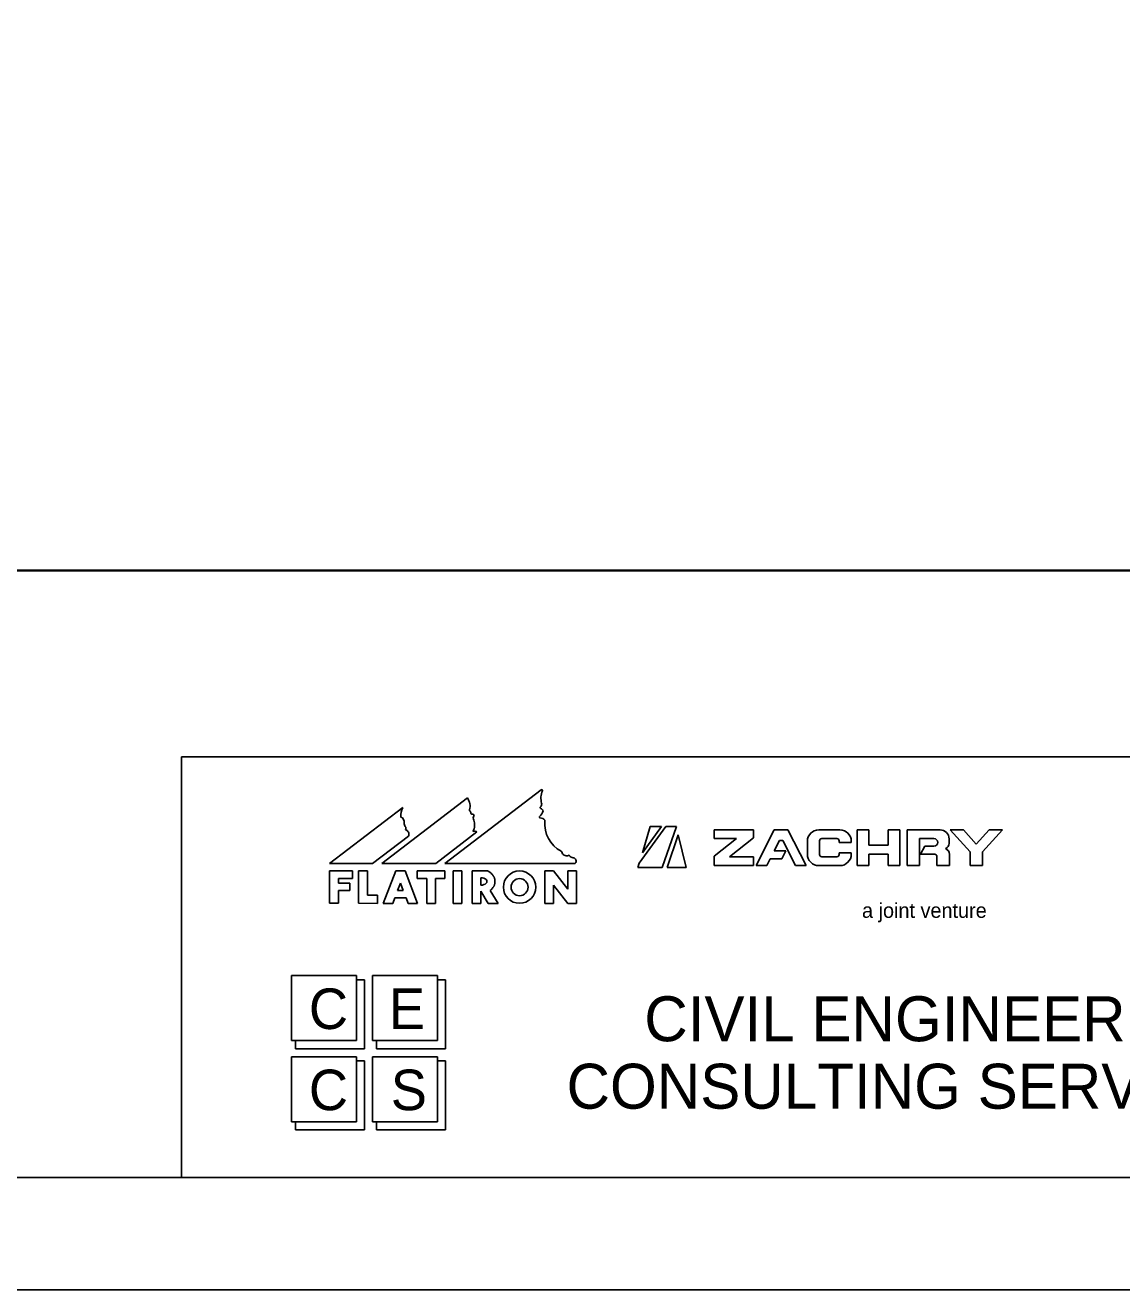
# Model space of a CAD drawing. Extents: x -2251 to 10196, y -13470 to 1199.
# Drawn here: x 1279.1 to 1522.8, y -2925.6 to -2644.4 of the extents above; entities that cross this region are included whole.
import ezdxf

# ---------------------------------------------------------------- set-up
doc = ezdxf.new("R2010")
doc.units = 0
for name, color, linetype in [('Level 3', 7, 'Continuous'), ('RD_SHT_Bndy', 7, 'Continuous'), ('RD_SHT_Iplotshp', 7, 'Continuous'), ('RD_SHT_Logo', 7, 'Continuous'), ('RD_SHT_Misc1', 7, 'Continuous'), ('RD_SHT_Snap', 7, 'Continuous'), ('RD_SHT_TX', 7, 'Continuous'), ('RD_TX_RoadID', 7, 'Continuous')]:
    doc.layers.add(name, color=color, linetype=linetype)

msp = doc.modelspace()

# ---------------------------------------------------------------- linework, layer by layer
at = {"layer": 'Level 3'}
msp.add_line((1465.07, -2863.99), (1465.07, -2863.99), dxfattribs=at)
msp.add_line((1465.07, -2863.99), (1465.07, -2863.99), dxfattribs=at)
msp.add_line((1465.07, -2863.99), (1465.07, -2863.99), dxfattribs=at)
msp.add_line((1465.07, -2863.99), (1465.07, -2863.99), dxfattribs=at)
at = {"layer": 'RD_SHT_Bndy'}
for p, q in [((103.1, -2900.65), (1778.1, -2900.65)), ((1791.65, -2925.65), (31.65, -2925.65))]:
    msp.add_line(p, q, dxfattribs=at)
msp.add_lwpolyline([(153.4, -1901.26), (1731.08, -1901.26), (1731.08, -2765.57), (153.4, -2765.57)], close=True, dxfattribs=at)
at = {"layer": 'RD_SHT_Iplotshp'}
msp.add_lwpolyline([(-3.35, -1825.65), (1796.65, -1825.65), (1796.65, -2925.65), (-3.35, -2925.65)], close=True, dxfattribs=at)
at = {"layer": 'RD_SHT_Logo'}
for p, q in [((1372.32, -2830.86), (1393.74, -2814.44)), ((1377.35, -2816.27), (1358.31, -2830.86)), ((1346.7, -2830.86), (1362.98, -2818.38)), ((1415.56, -2830.77), (1421.47, -2822.59)), ((1420.48, -2822.59), (1416.24, -2828.47)), ((1416.24, -2828.47), (1417.96, -2822.59)), ((1417.96, -2822.59), (1420.48, -2822.59)), ((1423.82, -2822.59), (1420.68, -2831.76)), ((1421.47, -2822.59), (1423.82, -2822.59)), ((1440.93, -2823.35), (1432.22, -2823.35)), ((1432.22, -2823.35), (1432.22, -2825.3)), ((1440.93, -2825.16), (1440.93, -2823.35)), ((1445.58, -2823.35), (1441.53, -2831.3)), ((1448.58, -2823.35), (1445.58, -2823.35)), ((1452.63, -2831.3), (1448.58, -2823.35)), ((1455.44, -2823.35), (1460.18, -2823.35)), ((1466.62, -2823.35), (1464.02, -2823.35)), ((1464.02, -2823.35), (1464.02, -2831.3)), ((1466.62, -2826.8), (1466.62, -2823.35)), ((1470.9, -2823.35), (1470.9, -2826.8)), ((1473.51, -2823.35), (1470.9, -2823.35)), ((1473.5, -2831.3), (1473.51, -2823.35)), ((1482.43, -2823.35), (1475.13, -2823.35)), ((1475.13, -2823.35), (1475.13, -2831.3)), ((1484.68, -2823.35), (1487.64, -2823.35)), ((1489.08, -2828.24), (1484.68, -2823.35)), ((1487.64, -2823.35), (1490.48, -2826.51)), ((1490.48, -2826.51), (1493.32, -2823.35)), ((1496.28, -2823.35), (1491.88, -2828.24)), ((1493.32, -2823.35), (1496.28, -2823.35)), ((1364.27, -2824.74), (1356.29, -2830.86)), ((1370.3, -2830.86), (1379.48, -2823.82)), ((1424.24, -2824.44), (1421.74, -2831.76)), ((1425.99, -2831.76), (1424.24, -2824.44)), ((1437.2, -2825.3), (1432.22, -2829.24)), ((1432.22, -2825.3), (1437.2, -2825.3)), ((1435.63, -2829.35), (1440.93, -2825.16)), ((1445.57, -2827.99), (1446.71, -2825.75)), ((1446.71, -2825.75), (1447.44, -2825.75)), ((1447.44, -2825.75), (1450.27, -2831.3)), ((1452.94, -2828.8), (1452.94, -2825.85)), ((1455.64, -2825.8), (1455.64, -2828.85)), ((1459.48, -2825.3), (1456.14, -2825.3)), ((1459.98, -2826.15), (1459.98, -2825.8)), ((1462.68, -2826.15), (1459.98, -2826.15)), ((1462.68, -2825.85), (1462.68, -2826.15)), ((1477.83, -2831.3), (1477.83, -2825.31)), ((1477.83, -2825.31), (1481.07, -2825.31)), ((1484.43, -2826.36), (1484.43, -2825.35)), ((1432.22, -2829.24), (1432.22, -2831.3)), ((1440.93, -2829.35), (1435.63, -2829.35)), ((1440.93, -2831.3), (1440.93, -2829.35)), ((1448.15, -2827.99), (1445.57, -2827.99)), ((1447.23, -2829.79), (1448.15, -2827.99)), ((1456.14, -2829.35), (1459.48, -2829.35)), ((1459.98, -2828.5), (1462.68, -2828.5)), ((1459.98, -2828.85), (1459.98, -2828.5)), ((1462.68, -2828.5), (1462.68, -2828.8)), ((1470.9, -2826.8), (1466.62, -2826.8)), ((1466.62, -2831.3), (1466.62, -2828.8)), ((1466.62, -2828.8), (1470.9, -2828.8)), ((1470.9, -2828.8), (1470.9, -2831.3)), ((1479.03, -2826.97), (1478.11, -2828.77)), ((1478.11, -2828.77), (1481.24, -2828.77)), ((1481.07, -2826.97), (1479.03, -2826.97)), ((1481.74, -2829.27), (1481.74, -2831.3)), ((1483.68, -2827.6), (1483.68, -2827.47)), ((1484.54, -2831.3), (1484.54, -2828.76)), ((1489.08, -2831.3), (1489.08, -2828.24)), ((1491.88, -2828.24), (1491.88, -2831.3)), ((1356.29, -2830.86), (1346.7, -2830.86)), ((1358.31, -2830.86), (1370.3, -2830.86)), ((1401.19, -2830.86), (1372.32, -2830.86)), ((1415.27, -2831.76), (1415.56, -2830.77)), ((1420.68, -2831.76), (1415.27, -2831.76)), ((1421.74, -2831.76), (1425.99, -2831.76)), ((1432.22, -2831.3), (1440.93, -2831.3)), ((1441.53, -2831.3), (1443.88, -2831.3)), ((1443.88, -2831.3), (1444.65, -2829.79)), ((1444.65, -2829.79), (1447.23, -2829.79)), ((1450.27, -2831.3), (1452.63, -2831.3)), ((1460.18, -2831.3), (1455.44, -2831.3)), ((1464.02, -2831.3), (1466.62, -2831.3)), ((1470.9, -2831.3), (1473.5, -2831.3)), ((1475.13, -2831.3), (1477.83, -2831.3)), ((1481.74, -2831.3), (1484.54, -2831.3)), ((1491.88, -2831.3), (1489.08, -2831.3)), ((1346.72, -2839.7), (1346.72, -2832.5)), ((1346.72, -2832.5), (1351.82, -2832.5)), ((1351.82, -2834.15), (1348.67, -2834.15)), ((1348.67, -2834.15), (1348.67, -2835.21)), ((1351.82, -2832.5), (1351.82, -2834.15)), ((1355.12, -2832.5), (1353.17, -2832.5)), ((1353.17, -2832.5), (1353.17, -2839.7)), ((1355.12, -2837.9), (1355.12, -2832.5)), ((1361.42, -2832.5), (1358.65, -2839.71)), ((1363.52, -2832.5), (1361.42, -2832.5)), ((1366.28, -2839.71), (1363.52, -2832.5)), ((1366.22, -2834.15), (1366.22, -2832.5)), ((1366.22, -2832.5), (1372.37, -2832.5)), ((1368.32, -2834.15), (1366.22, -2834.15)), ((1368.32, -2839.71), (1368.32, -2834.15)), ((1372.37, -2834.15), (1370.27, -2834.15)), ((1370.27, -2834.15), (1370.27, -2839.71)), ((1372.37, -2832.5), (1372.37, -2834.15)), ((1374.17, -2839.71), (1374.17, -2832.5)), ((1374.17, -2832.5), (1376.12, -2832.5)), ((1376.12, -2832.5), (1376.12, -2839.71)), ((1381.8, -2832.5), (1378.38, -2832.5)), ((1378.38, -2832.5), (1378.38, -2839.71)), ((1380.33, -2835.66), (1380.33, -2834.01)), ((1396.52, -2832.5), (1394.57, -2832.5)), ((1394.57, -2832.5), (1394.57, -2839.71)), ((1399.67, -2836.53), (1396.52, -2832.5)), ((1401.62, -2832.5), (1399.67, -2832.5)), ((1399.67, -2832.5), (1399.67, -2836.53)), ((1401.62, -2839.71), (1401.62, -2832.5)), ((1348.67, -2835.21), (1351.22, -2835.21)), ((1351.22, -2836.86), (1348.67, -2836.86)), ((1348.67, -2836.86), (1348.67, -2839.7)), ((1351.22, -2835.21), (1351.22, -2836.86)), ((1361.83, -2836.86), (1362.47, -2835.2)), ((1363.1, -2836.86), (1361.83, -2836.86)), ((1362.47, -2835.2), (1363.1, -2836.86)), ((1380.33, -2839.71), (1380.33, -2837.02)), ((1380.33, -2837.02), (1381.94, -2839.71)), ((1384.16, -2839.71), (1382.43, -2836.82)), ((1396.52, -2839.71), (1396.52, -2835.67)), ((1396.52, -2835.67), (1399.67, -2839.71)), ((1348.67, -2839.7), (1346.72, -2839.7)), ((1353.17, -2839.7), (1357.37, -2839.71)), ((1357.37, -2837.9), (1355.12, -2837.9)), ((1357.37, -2839.71), (1357.37, -2837.9)), ((1358.65, -2839.71), (1360.74, -2839.71)), ((1360.74, -2839.71), (1361.2, -2838.51)), ((1361.2, -2838.51), (1363.74, -2838.51)), ((1363.74, -2838.51), (1364.2, -2839.71)), ((1364.2, -2839.71), (1366.28, -2839.71)), ((1370.27, -2839.71), (1368.32, -2839.71)), ((1376.12, -2839.71), (1374.17, -2839.71)), ((1378.38, -2839.71), (1380.33, -2839.71)), ((1381.94, -2839.71), (1384.16, -2839.71)), ((1394.57, -2839.71), (1396.52, -2839.71)), ((1399.67, -2839.71), (1401.62, -2839.71)), ((1352.67, -2855.79), (1338.28, -2855.79)), ((1338.28, -2855.79), (1338.28, -2870.23)), ((1352.67, -2870.23), (1352.67, -2855.79)), ((1352.67, -2855.79), (1352.67, -2870.23)), ((1354.48, -2856.7), (1352.67, -2856.7)), ((1354.48, -2872.03), (1354.48, -2856.7)), ((1370.67, -2855.79), (1356.27, -2855.79)), ((1356.27, -2855.79), (1356.27, -2870.23)), ((1370.67, -2870.23), (1370.67, -2855.79)), ((1370.67, -2855.79), (1370.67, -2870.23)), ((1372.48, -2856.7), (1370.67, -2856.7)), ((1372.48, -2872.03), (1372.48, -2856.7)), ((1338.28, -2870.23), (1352.67, -2870.23)), ((1352.67, -2870.23), (1339.17, -2870.23)), ((1339.17, -2870.23), (1339.17, -2872.03)), ((1356.27, -2870.23), (1370.67, -2870.23)), ((1370.67, -2870.23), (1357.18, -2870.23)), ((1357.18, -2870.23), (1357.18, -2872.03)), ((1352.67, -2873.84), (1338.28, -2873.84)), ((1338.28, -2873.84), (1338.28, -2888.27)), ((1339.17, -2872.03), (1354.48, -2872.03)), ((1352.67, -2888.27), (1352.67, -2873.84)), ((1352.67, -2873.84), (1352.67, -2888.27)), ((1370.67, -2873.84), (1356.27, -2873.84)), ((1356.27, -2873.84), (1356.27, -2888.27)), ((1357.18, -2872.03), (1372.48, -2872.03)), ((1370.67, -2888.27), (1370.67, -2873.84)), ((1370.67, -2873.84), (1370.67, -2888.27)), ((1354.48, -2874.74), (1352.67, -2874.74)), ((1354.48, -2890.07), (1354.48, -2874.74)), ((1372.48, -2874.74), (1370.67, -2874.74)), ((1372.48, -2890.07), (1372.48, -2874.74)), ((1338.28, -2888.27), (1352.67, -2888.27)), ((1352.67, -2888.27), (1339.17, -2888.27)), ((1339.17, -2888.27), (1339.17, -2890.07)), ((1356.27, -2888.27), (1370.67, -2888.27)), ((1370.67, -2888.27), (1357.18, -2888.27)), ((1357.18, -2888.27), (1357.18, -2890.07)), ((1339.17, -2890.07), (1354.48, -2890.07)), ((1357.18, -2890.07), (1372.48, -2890.07))]:
    msp.add_line(p, q, dxfattribs=at)
for radius in [3.6, 1.9]:
    msp.add_circle((1388.95, -2836.1), radius, dxfattribs=at)
for centre, radius, start, end in [((1397.87, -2816.34), 4.17, 156.4699, 195.3053), ((1393.86, -2814.6), 0.2, 336.4699, 127.4657), ((1375.05, -2818.02), 2.89, 342.0343, 37.2653), ((1393.13, -2817.66), 0.749, 309.4079, 17.0499), ((1366.29, -2820.12), 3.74, 152.2252, 185.8662), ((1362.1, -2821.62), 1.21, 351.6466, 67.1294), ((1377.99, -2818.97), 0.2, 162.0343, 220.8638), ((1376.86, -2819.95), 1.3, 11.8745, 40.8638), ((1378.32, -2819.64), 0.2, 191.8745, 279.8173), ((1378.44, -2820.33), 0.499, 44.4799, 99.8173), ((1379.5, -2820.72), 0.843, 144.641, 212.5499), ((1378.65, -2820.12), 0.2, 324.641, 44.4799), ((1393.57, -2820.5), 0.2, 133.0036, 262.3069), ((1391.59, -2818.37), 2.7, 313.0036, 343.6807), ((1393.73, -2818.39), 0.2, 129.4079, 246.863), ((1393.31, -2822.44), 1.76, 45.283, 82.3069), ((1393.27, -2819.47), 0.973, 20.4113, 66.863), ((1364.29, -2821.94), 1, 171.6466, 221.9371), ((1363.11, -2823.01), 0.592, 327.6019, 41.9371), ((1363.3, -2824.33), 1.05, 337.4201, 73.1261), ((1375.8, -2822.18), 3.16, 331.2486, 18.4584), ((1378.92, -2824.44), 0.827, 48.0701, 115.7229), ((1394.4, -2821.33), 0.2, 353.8329, 45.283), ((1401.36, -2822.08), 6.8, 173.8329, 242.3928), ((1455.44, -2825.85), 2.5, 89.9984, 179.9984), ((1460.18, -2825.85), 2.5, 359.9984, 89.9984), ((1482.43, -2825.35), 2, 359.9984, 89.9984), ((1456.14, -2825.8), 0.5, 89.9984, 179.9984), ((1459.48, -2825.8), 0.5, 359.9984, 89.9984), ((1481.07, -2826.14), 0.831, 269.9984, 89.9984), ((1483.23, -2826.36), 1.2, 291.95, 359.9984), ((1398.12, -2828.28), 0.2, 9.0833, 62.3928), ((1399.35, -2828.09), 1.04, 189.0833, 295.769), ((1399.89, -2829.21), 0.2, 33.7112, 115.769), ((1400.89, -2828.54), 1.01, 213.7112, 268.6299), ((1455.44, -2828.8), 2.5, 179.9984, 269.9984), ((1456.14, -2828.85), 0.5, 179.9984, 269.9984), ((1459.48, -2828.85), 0.5, 269.9984, 359.9984), ((1460.18, -2828.8), 2.5, 269.9984, 359.9984), ((1481.24, -2829.27), 0.5, 359.9984, 89.9984), ((1483.34, -2828.76), 1.2, 359.9984, 73.7977), ((1400.86, -2829.74), 0.2, 78.9712, 88.6299), ((1400.75, -2830.3), 0.767, 320.912, 78.9712), ((1401.19, -2830.66), 0.2, 269.9984, 320.912)]:
    msp.add_arc(centre, radius, start, end, dxfattribs=at)
msp.add_ellipse((1380.33, -2834.83), major_axis=(1.36, 0), ratio=0.609965, start_param=4.712389, end_param=7.853982, dxfattribs=at)
msp.add_open_spline([(1382.43, -2836.82), (1382.51, -2836.76), (1382.59, -2836.7), (1382.81, -2836.49), (1382.95, -2836.34), (1383.13, -2836.07), (1383.19, -2835.97), (1383.29, -2835.77), (1383.34, -2835.66), (1383.41, -2835.44), (1383.44, -2835.32), (1383.47, -2835.08), (1383.48, -2834.96), (1383.48, -2834.71), (1383.47, -2834.59), (1383.44, -2834.35), (1383.41, -2834.23), (1383.34, -2834.01), (1383.29, -2833.9), (1383.19, -2833.7), (1383.13, -2833.6), (1382.95, -2833.33), (1382.81, -2833.18), (1382.52, -2832.91), (1382.37, -2832.8), (1382.08, -2832.63), (1381.94, -2832.56), (1381.8, -2832.5)], degree=3, dxfattribs=at)
at = {"layer": 'RD_SHT_Misc1'}
msp.add_lwpolyline([(1796.65, -2925.65), (1796.68, -1825.65), (96.68, -1825.6), (96.65, -2925.6)], close=True, dxfattribs=at)
at = {"layer": 'RD_SHT_Snap'}
msp.add_lwpolyline([(8.15, -1825.65), (1808.15, -1825.65), (1808.15, -2925.65), (8.15, -2925.65)], close=True, dxfattribs=at)
at = {"layer": 'RD_SHT_TX'}
for p, q in [((1313.76, -2900.65), (1313.76, -2807.15)), ((1313.76, -2900.65), (1313.76, -2807.15)), ((1313.76, -2807.15), (1778.1, -2807.15))]:
    msp.add_line(p, q, dxfattribs=at)
at = {"layer": 'RD_TX_RoadID'}
msp.add_lwpolyline([(150.54, -2765.73), (1733.93, -2765.73), (1733.93, -1962.61), (150.54, -1962.61)], close=True, dxfattribs=at)

# ---------------------------------------------------------------- texts
at = {"layer": 'RD_SHT_Logo'}
msp.add_text('a joint venture', height=3.3, rotation=359.9984, dxfattribs=at).set_placement((1465.08, -2842.93))
for s, height, p in [('C', 9.02, (1342.11, -2867.66)), ('E', 9.02, (1359.9, -2867.66)), ('CIVIL ENGINEERING', 10, (1416.67, -2870.38)), ('C', 9.02, (1342.11, -2885.71)), ('S', 9.02, (1360.32, -2885.71)), ('CONSULTING SERVICES, INC.', 10, (1399.39, -2885.38))]:
    msp.add_text(s, height=height, dxfattribs=at).set_placement(p)

doc.saveas('drawing.dxf')
